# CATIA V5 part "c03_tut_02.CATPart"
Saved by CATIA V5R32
Part number: c03tut2
Bounding box of the stored display mesh (mm): x 0 to 0, y -39.994 to 149.998, z -40 to 39.984
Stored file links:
  D:\PROJECTS\Project 2022\CATIA V5 6R 2022\Resources\Tutorial Files\c03_catia_v5_6r2021_tut\c03_tut_02.CATPart
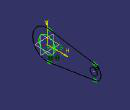
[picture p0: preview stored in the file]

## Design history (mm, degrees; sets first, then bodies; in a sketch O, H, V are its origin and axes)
Body1 (main body)
  Sketch1 on yz-plane, origin (0, 0, 0), H (0, 1, 0), V (0, 0, 1)
    arc A1 centre (0, 0) radius 40 from (6.1538, 39.5238) to (6.1538, -39.5238) ccw
    point P1 (0, -40)
    arc A2 centre (130, 0) radius 20 from (133.0769, -19.7619) to (133.0769, 19.7619) ccw
    point P2 (130, 0)
    line L1 (6.1538, 39.5238) -> (133.0769, 19.7619)
    line L2 (6.1538, -39.5238) -> (133.0769, -19.7619)
    circle A3 centre (0, 0) radius 22.5
    circle A4 centre (130, 0) radius 10
    radius A3 = 22.5
    coincidence: A1 P1, P1 V, P2 H
    tangency: L1 A1, L1 A2, L2 A1, L2 A2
